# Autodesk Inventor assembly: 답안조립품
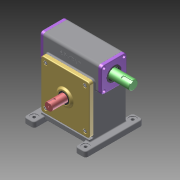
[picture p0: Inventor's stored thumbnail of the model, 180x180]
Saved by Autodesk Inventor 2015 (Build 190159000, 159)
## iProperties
Created: 2025-06
Part Number: 답안조립품
Document SubType Name: Assembly
Designer: User
Author: User
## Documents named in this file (12)
- C:\Users\User\Downloads\750603V1008\답안조립품.iam
- C:\Users\User\Downloads\750603V1008\가져온 구성요소\6각 구멍붙이 볼트 M8x20\6각 구멍붙이 볼트 M8x20.ipt
- C:\Users\User\Downloads\750603V1008\가져온 구성요소\깊은 홈 볼 베어링 6206\깊은 홈 볼 베어링 6206.ipt
- C:\Users\User\Downloads\750603V1008\가져온 구성요소\깊은 홈 볼 베어링 6209\깊은 홈 볼 베어링 6209.ipt
- C:\Users\User\Downloads\750603V1008\가져온 구성요소\뒷커버\뒷커버.ipt
- C:\Users\User\Downloads\750603V1008\본체.ipt
- C:\Users\User\Downloads\750603V1008\가져온 구성요소\앞커버\앞커버.ipt
- C:\Users\User\Downloads\750603V1008\가져온 구성요소\오일 실 30 42 7\오일 실 30 42 7.ipt
- C:\Users\User\Downloads\750603V1008\가져온 구성요소\오일 실 35 55 11\오일 실 35 55 11.ipt
- C:\Users\User\Downloads\750603V1008\가져온 구성요소\웜 샤프트\웜 샤프트.ipt
- C:\Users\User\Downloads\750603V1008\가져온 구성요소\웜 휠 커버\웜 휠 커버.ipt
- C:\Users\User\Downloads\750603V1008\가져온 구성요소\웜 휠\웜 휠.ipt
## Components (4 placed, 1 different names)
1. 6각 구멍붙이 볼트 M8x20:1
2. 6각 구멍붙이 볼트 M8x20:2
3. 6각 구멍붙이 볼트 M8x20:3
4. 6각 구멍붙이 볼트 M8x20:4
